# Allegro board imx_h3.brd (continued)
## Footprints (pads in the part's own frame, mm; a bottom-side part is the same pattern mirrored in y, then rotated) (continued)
RC0402_25
  round 0.635 smd: 1(-0.508,0) 2(0.508,0)
RC0603_OV
  oval 0.889x1.143 smd: 1(-0.762,0) 2(0.762,0)
RC0805_OV
  oval 0.889x1.524 smd: 1(-0.965,0) 2(0.965,0)
RCA8_16
  rect 0.66x0.406 smd: 1(-0.711,1.802) 8(-0.711,-1.802) 9(0.711,-1.802) 16(0.711,1.802)
  rect 0.66x0.305 smd: 2(-0.711,1.251) 3(-0.711,0.751) 4(-0.711,0.25) 5(-0.711,-0.25) 6(-0.711,-0.751) 7(-0.711,-1.251) 10(0.711,-1.251) 11(0.711,-0.751) 12(0.711,-0.25) 13(0.711,0.25) 14(0.711,0.751) 15(0.711,1.251)
SC70-5
  rect 0.406x0.813 smd: 1(-0.65,-1.079) 2(0,-1.079) 3(0.65,-1.079) 4(0.65,1.079) 5(-0.65,1.079)
SC70_3
  rect 0.711x0.889 smd: 1(-0.648,-0.952) 2(0.648,-0.952) 3(0,0.952)
SOD123
  rect 1.016x1.27 smd: A(1.651,0) C(-1.651,0)
SOD-123
  rect 1.321x1.219 smd: A(-1.626,0) C(1.626,0)
SOT23
  rect 0.762x1.219 smd: 1(-1.016,-1.092) 2(1.016,-1.092) 3(0,1.092)
SOT23-5
  rect 0.61x1.118 smd: 1(-1,-1.4) 2(-0.05,-1.4) 3(0.9,-1.4) 4(0.9,1.45) 5(-1,1.45)
SOT23-5_A
  rect 1.016x0.762 smd: 1(-1.3,0.95) 2(-1.3,0) 3(-1.3,-0.95) 4(1.3,-0.95) 5(1.3,0.95)
SOT23_5S
  rect 0.686x0.991 smd: 1(-0.953,-1.295) 2(0,-1.295) 3(0.953,-1.295) 4(0.953,1.295) 5(-0.953,1.295)
SOT223
  rect 1.194x2.21 smd: 1(-2.3,-3.1) 2(0,-3.1) 3(2.3,-3.1)
  rect 3.734x2.21 smd: 4(0,3.1)
SOT363
  rect 0.406x0.508 smd: 1(-0.65,-0.95) 2(0,-0.95) 3(0.65,-0.95) 4(0.65,0.95) 5(0,0.95) 6(-0.65,0.95)
SOT-23
  rect 1.016x1.397 smd: 1(-0.95,-1.1) 2(0.95,-1.1) 3(0,1.1)
SSOP16
  rect 2.032x0.406 smd: 1(-3.48,2.276) 2(-3.48,1.626) 3(-3.48,0.975) 4(-3.48,0.325) 5(-3.48,-0.325) 6(-3.48,-0.975) 7(-3.48,-1.626) 8(-3.48,-2.276) 9(3.48,-2.276) 10(3.48,-1.626) 11(3.48,-0.975) 12(3.48,-0.325) 13(3.48,0.325) 14(3.48,0.975) 15(3.48,1.626) 16(3.48,2.276)
SW2_SPST_PB_RA
  round 0.254 hole 1.245x0.889 unplated: (-1.499,0)
  round 0.254 hole 0.889 unplated: (1.499,0)
  rect 1.016x1.219 smd: 1(1.93,2.718) 2(1.93,-2.718)
  rect 1.397x1.27 smd: 3(-1.041,-2.667) 4(-1.041,2.667)
SW_SPST_PB_4P8X3P5_SM
  rect 1.6x1.016 smd: 1(2.625,0.85) 2(2.625,-0.85) 3(-2.625,0.85) 4(-2.625,-0.85)
TESTPOINT_35MIL
  round 0.889 smd: 1(0,0)
TESTPOINT_060_035MIL
  round 1.524 hole 0.889: 1(0,0)
TSOP48
  rect 2.54x0.305 smd: 1(-9.677,5.753) 2(-9.677,5.253) 3(-9.677,4.752) 4(-9.677,4.252) 5(-9.677,3.752) 6(-9.677,3.251) 7(-9.677,2.751) 8(-9.677,2.25) 9(-9.677,1.75) 10(-9.677,1.25) 11(-9.677,0.749) 12(-9.677,0.249) 13(-9.677,-0.249) 14(-9.677,-0.749) 15(-9.677,-1.25) 16(-9.677,-1.75) 17(-9.677,-2.25) 18(-9.677,-2.751) 19(-9.677,-3.251) 20(-9.677,-3.752) 21(-9.677,-4.252) 22(-9.677,-4.752) 23(-9.677,-5.253) 24(-9.677,-5.753) 25(9.677,-5.753) 26(9.677,-5.253) 27(9.677,-4.752) 28(9.677,-4.252) 29(9.677,-3.752) 30(9.677,-3.251) 31(9.677,-2.751) 32(9.677,-2.25) 33(9.677,-1.75) 34(9.677,-1.25) 35(9.677,-0.749) 36(9.677,-0.249) 37(9.677,0.249) 38(9.677,0.749) 39(9.677,1.25) 40(9.677,1.75) 41(9.677,2.25) 42(9.677,2.751) 43(9.677,3.251) 44(9.677,3.752) 45(9.677,4.252) 46(9.677,4.752) 47(9.677,5.253) 48(9.677,5.753)
TSSOP14_A
  rect 1.524x0.356 smd: 1(-2.959,1.951) 2(-2.959,1.3) 3(-2.959,0.65) 4(-2.959,0) 5(-2.959,-0.65) 6(-2.959,-1.3) 7(-2.959,-1.951) 8(2.959,-1.951) 9(2.959,-1.3) 10(2.959,-0.65) 11(2.959,0) 12(2.959,0.65) 13(2.959,1.3) 14(2.959,1.951)
unnamed#2
  round 1.016 smd: (0,0)
VLF5020
  custom 0.524x0.524 smd: 1(-1.699,0) 2(1.699,0)
XTAL2-3P2X1P5-SM
  rect 1.092x1.905 smd: 1(-1.25,0) 2(1.25,0)
XTAL_CS10_SM
  rect 2.007x2.489 smd: 1(-2.248,0) 2(2.248,0)
XTLOSC4_3P2X2P5MM_SM
  rect 1.397x1.194 smd: 1(-1.1,-0.8) 2(1.1,-0.8) 3(1.1,0.8) 4(-1.1,0.8)

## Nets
3V3_DEBUG: C205.1 C206.1 U34.16(VUSB33) U34.17(VUSB33_MON)
3V3_GATED: C29.1 C58.1 C147.1 C150.1 C152.1 C154.1 C155.1 C157.1 C183.1 C198.1 C215.1 C216.1 C221.1 C223.2 C249.1 C250.1 C271.1 C284.1 C285.1 C286.1 C287.1 C288.1 C294.1 D44.3(CATHODE) J20.2(3.3V_1) J20.3(RESERVED1) J20.4(GND7) J20.10(UIM_DATA) J20.12(UIM_CLK) L1.2 L12.1 L19.2 R9.1 R12.1 R13.2 R14.2 R64.1 R77.2 R81.1 R82.1 R128.1 R178.1 R204.1 U3.9(VDDIO) U14.1(VIN) U19.20(VDDIO) U41.7(VDDD)
3V3_GATED_EN: R143.1 U14.3(CE) U17.3(IO0_2) U29.3(EN)
3V3_ISM: C160.1 C161.1 C162.1 C163.1 C164.1 C165.1 C168.1 C169.1 C170.1 C190.1 C293.1 J11.6(B3) U4.1(VREFH) U4.19(VDD) U4.35(VBAT2) U4.43(VBAT1(RF)) U4.55(VDD1) U4.56(VDDAD) U42.5(VOUT)
3V3_MAIN: C85.1 C210.1 C211.1 C218.2 C227.1 C228.1 C229.1 C230.1 C281.1 C282.1 C283.1 L15.2 L18.2 R137.1 R138.1 R174.1 R212.1 U25.5(VDDA33_5) U25.10(VDDA33_10) U25.15(VDD33_15) U25.23(VDD33_23) U25.27(VBUS_DET) U25.29(VDD33_29) U25.36(VDD33_36)
4V2_BACKUP: C185.1 C196.1 C208.1 C220.1 C222.1 C292.1 L11.1 L20.1 Q6.4(S) Q13.4(S) R135.1 R155.1 R158.1 R172.1 R210.1 U16.2(VIN) U20.2(VIN) U28.1(VIN) U29.1(VIN) U30.5(3V3) U42.1(VIN)
4V2_BUCK: C201.1 C275.1 C276.1 C277.1 L16.2 Q5.4(S) R176.2 U22.1(BD) U22.7(BIAS)
4V2_PG: R155.2 S1.1(A1) U22.6(PG) U30.2(IN_A)
5V: C186.1 C256.1 C258.1 C259.1 C262.1 C278.1 C279.1 C280.1 C290.1 D11.C J13.2 J13.4 J13.7 J13.8 J13.11 J13.13 J13.39 J13.41 R98.1
5V_DEBUG: C35.1 C134.1 L5.1 Q17.1(GATE) Q18.1(GATE) Q19.1(GATE) Q20.1(GATE) R19.1 R68.1 R69.1 R214.2 U34.11(VDD)
5V_LCD_EN: U16.3(EN) U17.4(IO0_3)
5V_MAIN: C104.1 C105.1 C106.1 C202.1 C233.1 D45.C(CATHODE) F1.1 Q15.2(ANODE1) Q15.4(ANODE2) R44.1 TVS1.2 TVS2.2 U1.E17(VDD5V) U22.4(VIN) U22.5(RUN/SS)
5V_MAIN_PRESENT: J5.2 R44.2 U1.D3(SSP2_SS1/SSP2_D4/SSP2_D1/USB1_O) U30.1(IN_B)
5V_USB: C195.1 C231.1 C232.1 D12.C R132.1 U32.2(IN) U33.2(IN)
5V_USB_REG_EN: R158.2 U20.3(EN) U40.8(Y3)
GND: ANT1.2(GND) C1.2 C2.2 C3.2 C4.2 C5.2 C6.2 C7.2 C8.2 C9.2 C10.2 C11.2 C12.2 C13.2 C14.2 C15.2 C16.2 C17.2 C18.2 C19.2 C20.2 C21.2 C22.2 C23.2 C25.2 C26.2 C27.2 C28.2 C29.2 C30.2 C31.2 C32.2 C33.2 C34.2 C35.2 C51.2 C52.2 C57.2 C58.2 C59.2 C60.2 C61.2 C62.2 C63.2 C64.2 C65.2 C66.2 C67.2 C68.2 C69.2 C70.2 C71.2 C72.2 C73.2 C74.2 C75.2 C76.2 C77.2 C78.2 C79.2 C80.2 C81.2 C82.2 C83.2 C84.2 C85.2 C86.2 C87.2 C88.2 C89.2 C90.2 C91.2 C92.2 C93.2 C94.2 C95.2 C96.2 C97.2 C98.2 C99.2 C100.2 C101.2 C102.2 C103.2 C105.2 C106.2 C107.2 C108.1 C109.2 C110.2 C111.2 C112.2 C113.2 C114.2 C115.2 C116.2 C117.2 C118.2 C119.2 C120.2 C121.2 C122.2 C123.2 C124.2 C125.2 C126.2 C127.2 C128.2 C129.2 C130.2 C131.2 C132.2 C133.2 C134.2 C135.2 C136.2 C137.2 C138.2 C139.2 C140.2 C141.2 C142.1 C143.2 C144.2 C145.2 C146.1 C147.2 C148.2 C149.2 C150.2 C151.2 C152.2 C153.2 C154.2 C155.2 C156.2 C157.2 C158.2 C159.2 C160.2 C161.2 C162.2 C163.2 C164.2 C165.2 C166.1 C167.2 C168.2 C169.2 C170.2 C171.2 C172.1 C173.2 C174.2 C175.2 C176.2 C178.2 C179.2 C180.2 C183.2 C184.2 C185.2 C186.2 C187.2 C188.2 C189.2 C190.2 C192.2 C194.2 C195.2 C196.2 C197.1 C198.2 C199.2 C200.1 C201.2 C202.2 C203.2 C205.2 C206.2 C207.2 C208.2 C209.2 C210.2 C211.2 C212.2 C213.2 C214.2 C215.2 C216.2 C217.2 C219.1 C220.2 C221.2 C222.2 C224.1 C225.2 C226.2 C227.2 C228.2 C229.2 C230.2 C231.2 C232.2 C233.2 C234.2 C235.2 C236.2 C237.2 C238.2 C239.2 C240.2 C241.2 C243.2 C244.2 C245.2 C246.2 C247.2 C248.2 C249.2 C250.2 C251.2 C252.2 C253.2 C254.2 C255.2 C256.2 C257.2 C258.2 C259.2 C260.2 C261.2 C262.2 C263.2 C264.2 C265.2 C266.2 C267.2 C268.2 C269.2 C270.2 C271.2 C272.2 C273.2 C274.2 C275.2 C276.2 C277.2 C278.2 C279.2 C280.2 C281.2 C282.2 C283.2 C284.2 C285.2 C286.2 C287.2 C288.2 C289.2 C290.2 C291.2 C292.2 C293.2 C294.2 C295.2 C296.2 C297.2 C298.2 C300.2 D17.A D43.3 D44.1(ANODE) E5.1 E6.1 FL1.1(GND1) FL1.2(GND2) FL2.1(GND1) FL2.2(GND2) FL3.1(GND1) FL3.2(GND2) FL4.1(GND1) FL4.2(GND2) FL5.1(GND1) FL5.2(GND2) FL6.1(GND1) FL6.2(GND2) FL7.1(GND1) FL7.2(GND2) FL8.1(GND1) FL8.2(GND2) J5.3 J9.2(GND1) J9.3(GND2) J10.2(GND1) J10.3(GND2) J11.2(B1) J12.2(GND1) J12.3(GND2) J13.6 J13.12 J13.18 J13.23 J13.24 J13.30 J13.36 J13.42 J13.48 J13.54 J13.60 J13.93 J13.103 J13.SH1 J13.SH2 J13.SH3 J13.SH4 J13.SH5 J13.SH6 J13.SH7 J13.SH8 J14.2(GND1) J14.3(GND2) J16.2 J17.3 J20.6(1.5V_1) J20.8(UIM_PWR) J20.9(GND1) J20.13(REFCLK+) J20.14(UIM_RESET) J20.24(+3.3VAUX) J20.26(GND9) J20.48(1.5V_3) J20.50(GND12) J20.52(3.3V_2) J23.2 L4.2 L13.2 L23.1 L25.1 L26.1 L30.2 P2.9 P2.10 Q4.2(SOURCE) Q9.2(SOURCE) Q15.1(CATHODE) Q16.2(SOURCE) R3.2 R11.2 R15.2 R16.1 R18.1 R20.2 R27.2 R42.2 R43.2 R57.2 R58.2 R75.2 R76.2 R78.1 R80.2 R96.2 R103.2 R119.2 R120.2 R122.2 R123.2 R129.2 R130.2 R131.2 R136.2 R141.2 R142.2 R143.2 R147.2 R148.2 R150.2 R166.1 R167.1 R168.2 R169.1 R169.2 R170.2 R171.1 R171.2 R173.2 R175.2 R177.2 R208.1 R214.1 S1.3(B2) S1.4(B1) SW3.2 SW3.4 SW5.2 SW6.1 SW7.2 SW7.4 SW8.1 T1.7(NC) T1.8(GND) T1.13(GND_13) T1.14(GND_14) TP3.1(TP) TP4.1(TP) TP5.1(TP) TVS1.1 TVS2.1 U1.A1(VSS1) U1.A9(VSS2) U1.A17(DCDC_GND) U1.B7(VSS3) U1.B11(VSSA2_A) U1.B13(VSSA1) U1.C10(TESTMODE) U1.C16(VSS4) U1.E5(VSS5) U1.E15(VSS6) U1.F14(VSSIO_EMI10) U1.F16(VSSIO_EMI9) U1.H3(VSS7) U1.H9(VSS8) U1.H10(VSS9) U1.H11(VSS10) U1.H12(VSS11) U1.H14(VSSIO_EMI8) U1.H16(VSS12) U1.J11(VSS13) U1.J12(VSS14) U1.J15(VSS15) U1.K9(VSS16) U1.K10(VSS17) U1.K11(VSS18) U1.L10(VSS19) U1.L11(VSS20) U1.L12(VSSIO_EMI7) U1.M14(VSS21) U1.M16(VSSIO_EMI6) U1.N4(VSS22) U1.P14(VSSIO_EMI4) U1.P16(VSSIO_EMI5) U1.R10(VSSIO_EMI_11) U1.R12(VSSIO_EMI1) U1.T14(VSSIO_EMI3) U1.U1(VSS23) U1.U17(VSSIO_EMI2) U2.A3(VSS1) U2.A7(VSSQ2) U2.B2(VSSQ3) U2.B8(VSSQ1) U2.D2(VSSQ4) U2.D8(VSSQ5) U2.E3(VSS2) U2.E7(VSSQ6) U2.F2(VSSQ7) U2.F8(VSSQ8) U2.H2(VSSQ9) U2.H8(VSSQ10) U2.J3(VSS3) U2.J7(VSSDL) U2.N1(VSS4) U2.P9(VSS5) U3.25(VSS) U4.2(VREFL) U4.3(VSSAD) U4.4(VSS1) U4.20(VSS2) U4.36(GND) U4.38(GND_PA2(RF)) U4.40(GND_PA1(RF)) U4.61(VSS3) U4.62(VSS4) U5.13(VSS1) U5.36(VSS2) U14.2(GND) U15.58(RF_GND) U15.75(VSS_1) U15.76(VSS_2) U15.77(VSS_3) U15.78(VSS_4) U15.79(VSS_5) U15.84(VSS_6) U15.85(VSS_7) U15.86(VSS_8) U15.87(VSS_9) U15.88(VSS_10) U15.93(VSS_11) U15.94(VSS_12) U15.95(VSS_13) U15.96(VSS_14) U15.97(VSS_15) U15.104(VSS_16) U15.105(VSS_17) U15.106(VSS_18) U15.115(VSS_19) U16.1(PGND) U16.5(AGND) U16.7(EP) U17.9(VSS) U17.23(A1) U17.25(EP) U19.1(GND1) U19.3(GND2) U19.7(AGND) U19.33(GND3-PAD) U20.1(PGND) U20.5(AGND) U20.7(EP) U22.11(GND) U25.37(VSS_EPAD) U28.2(GND) U29.2(GND) U30.3(DGND) U31.3(DGND) U32.1(GND) U32.9(PAD) U33.1(GND) U33.9(PAD) U34.13(VSS) U34.23(VSSOSC) U34.25(EP) U40.7(GND) U41.5(N\R\D\) U41.6(N\W\R\) U41.10(GND) U41.16(GNDA) U42.2(GND) Y3.2(GND#2) Y3.4(GND#4) Y4.2 Y4.4 Y5.2(GND#2) Y5.4(GND#4) Y7.2(GND#2) Y7.4(GND#4) Y8.2(GND#2) Y8.4(GND#4)
VBUS_BOT: C235.1 C239.1 L22.1 U32.6(OUT2)
VBUS_MODEM: C237.1 C238.1 L24.1 U33.6(OUT2)
VBUS_OTG: C236.1 C241.1 C254.1 D4.C L3.1 R93.2
VBUS_TOP: C234.1 C240.1 L21.1 U32.7(OUT1)
VDD1P5_1V5: C119.1 C120.1 C121.1 C122.1 C123.1 U1.D16(VDD1P5)
VDD_1V5: C291.1 J13.111 J13.113 J13.115
VDD_4P2: C129.1 C130.1 C131.1 C132.1 C133.1 U1.A13(VDD4P2)
VDD_XTAL: C140.1 SW2.2 U1.C12(VDDXTAL)
ADC_BATT: C153.1 R165.2 U1.C15(LRADC0)
BKGD: J11.1(A1) U4.34(PTA4/ACMP1O/BKGD/MS)
BT_ACTIVE: J20.41(RESERVED5) R101.1
BT_HOST_WAKE: J20.43(RESERVED6) U17.13(IO1_3)
BT_RESET_B: J20.42(LED_WWAN#) U17.16(IO1_6)
BUTTON_1: R127.1 R151.1 U1.B5(SSP0_DATA4/SSP2_D0/GPIO2_4)
BUTTON_2: R124.1 R144.1 U1.C5(SSP0_DATA5/SSP2_D3/GPIO2_5)
BUTTON_3: R140.1 R153.2 U1.D5(SSP0_DATA6/SSP2_CMD/GPIO2_6)
BUTTON_4: R126.1 R152.2 U1.D10(SSP0_DETECT/GPIO2_9)
DCDC_VDDA_1V8: C1.1 C2.1 C3.1 C4.1 C5.1 C6.1 C7.1 C8.1 C9.1 C10.1 C11.1 C12.1 C13.1 C14.1 C15.1 C16.1 C17.1 C18.1 C19.1 C20.1 C21.1 C22.1 C23.1 C24.1 C74.1 C75.1 C76.1 C77.1 C78.1 C79.1 C80.1 C81.1 C83.1 C84.1 C86.1 C87.1 C88.1 C89.1 C90.1 C91.1 C92.1 C93.1 C94.1 C95.1 C98.1 C109.1 C110.1 C111.1 C112.1 C113.1 C245.1 C246.1 C257.1 C261.1 C264.1 J13.1 J13.17 J13.19 J13.25 R2.1 U1.B16(DCDC_VDDA) U1.C13(VDDA1) U1.F8(VDDIO18_0) U1.F9(VDDIO18_1) U1.G8(VDDIO18_2) U1.G9(VDDIO18_3) U1.G13(VDDIO_EMI_8_1) U1.G15(VDDIO_EMI_8_2) U1.G17(VDDIO_EMI_8_3) U1.J13(VDDIO_EMIQ2) U1.K15(VDDIO_EMIQ1) U1.L13(VDDIO_EMI_7) U1.M10(VDDIO_EMI_0) U1.M11(VDDIO_EMI_3_1) U1.M12(VDDIO_EMI_3_2) U1.N13(VDDIO_EMI_3_3) U1.N15(VDDIO_EMI_6) U1.P11(VDDIO_EMI_1) U1.R13(VDDIO_EMI_3_4) U1.R15(VDDIO_EMIQ0) U2.A1(VDD1) U2.A9(VDDQ6) U2.C1(VDDQ2) U2.C3(VDDQ3) U2.C7(VDDQ4) U2.C9(VDDQ5) U2.E1(VDD2) U2.E9(VDDQ1) U2.G1(VDDQ7) U2.G3(VDDQ8) U2.G7(VDDQ9) U2.G9(VDDQ10) U2.J1(VDDL) U2.J9(VDD3) U2.M9(VDD4) U2.R1(VDD5)
DCDC_VDDD_1V2: C57.1 C59.1 C60.1 C62.1 C63.1 C114.1 C115.1 C116.1 C117.1 C118.1 U1.D17(DCDC_VDDD) U1.F10(VDDD0) U1.F11(VDDD1) U1.F12(VDDD2) U1.G10(VDDD3) U1.G11(VDDD4) U1.G12(VDDD5) U1.K12(VDDD6)
DCDC_VDDIO_3V3: C51.1 C52.1 C64.1 C65.1 C66.1 C67.1 C69.1 C70.1 C71.1 C72.1 C73.1 C96.1 C97.1 C99.1 C100.1 C101.1 C102.1 C103.1 C187.1 C217.1 C255.1 C260.1 C265.1 C266.1 C272.1 J13.5 J13.45 J13.47 J13.49 J20.1(WAKE#) J20.32(SMB_DATA) P2.1 R17.1 R25.1 R26.1 R45.2 R49.2 R51.1 R52.1 R53.1 R54.1 R55.1 R56.1 R66.2 R104.1 R105.1 R109.1 R118.1 R124.2 R126.2 R134.2 R140.2 R151.2 R213.2 U1.A7(VDDIO33_8) U1.C17(DCDC_VDDIO) U1.E6(VDDIO33_0) U1.E16(VDDIO33_7) U1.G3(VDDIO33_1) U1.H8(VDDIO33_5_1) U1.J8(VDDIO33_5_2) U1.J9(VDDIO33_5_3) U1.J10(VDDIO33_5_4) U1.N3(VDDIO33_4) U1.N17(VDDIO33_EMI) U5.12(VCC1) U5.37(VCC2) U17.18(A0) U17.21(VDD) U17.24(A2) U31.5(3V3) U40.14(VCC)
DDR2_A0: U1.U15(EMI_A00) U2.M8(A0)
DDR2_A1: U1.U12(EMI_A01) U2.M3(A1)
DDR2_A2: U1.U14(EMI_A02) U2.M7(A2)
DDR2_A3: U1.T11(EMI_A03) U2.N2(A3)
DDR2_A4: U1.U10(EMI_A04) U2.N8(A4)
DDR2_A5: U1.R11(EMI_A05) U2.N3(A5)
DDR2_A6: U1.R9(EMI_A06) U2.N7(A6)
DDR2_A7: U1.N11(EMI_A07) U2.P2(A7)
DDR2_A8: U1.U9(EMI_A08) U2.P8(A8)
DDR2_A9: U1.P10(EMI_A09) U2.P3(A9)
DDR2_A10: U1.U13(EMI_A10) U2.M2(A10)
DDR2_A11: U1.T10(EMI_A11) U2.P7(A11)
DDR2_A12: U1.U11(EMI_A12) U2.R2(A12)
DDR2_A13: U1.T9(EMI_A13) U2.R8(NC/A13)
DDR2_A14: U1.N10(EMI_A14) U2.R3(NC/A14)
DDR2_BA0: U1.T16(EMI_BA0) U2.L2(BA0)
DDR2_BA1: U1.T12(EMI_BA1) U2.L3(BA1)
DDR2_BA2: U1.N12(EMI_BA2) U2.L1(NC/BA2)
DDR2_CAS_B: U1.U16(E\M\I\_\C\A\S\) U2.L7(CAS#)
DDR2_CKE: R58.1 U1.T13(EMI_CKE) U2.K2(CKE)
DDR2_CLK: R1.1 U1.L17(EMI_CLK) U2.J8(CK)
DDR2_CLK_B: R1.2 U1.L16(E\M\I\_\C\L\K\) U2.K8(CK#)
DDR2_CS_B: U1.P12(E\M\I\_\C\E\0\) U2.L8(CS#)
DDR2_D00: U1.N16(EMI_D00) U2.H1(DQ4)
DDR2_D01: U1.M13(EMI_D01) U2.G2(DQ1)
DDR2_D02: U1.P15(EMI_D02) U2.H3(DQ3)
DDR2_D03: U1.N14(EMI_D03) U2.F1(DQ6)
DDR2_D04: U1.P13(EMI_D04) U2.H7(DQ2)
DDR2_D05: U1.P17(EMI_D05) U2.H9(DQ5)
DDR2_D06: U1.L14(EMI_D06) U2.F9(DQ7)
DDR2_D07: U1.M17(EMI_D07) U2.G8(DQ0)
DDR2_D08: U1.G16(EMI_D08) U2.C8(DQ8)
DDR2_D09: U1.H15(EMI_D09) U2.D7(DQ10)
DDR2_D10: U1.G14(EMI_D10) U2.C2(DQ9)
DDR2_D11: U1.J14(EMI_D11) U2.D3(DQ11)
DDR2_D12: U1.H13(EMI_D12) U2.D1(DQ12)
DDR2_D13: U1.H17(EMI_D13) U2.D9(DQ13)
DDR2_D14: U1.F13(EMI_D14) U2.B1(DQ14)
DDR2_D15: U1.F17(EMI_D15) U2.B9(DQ15)
DDR2_DQM0: U1.M15(EMI_DQM0) U2.F3(LDM)
DDR2_DQM1: U1.F15(EMI_DQM1) U2.B3(UDM)
DDR2_DQS0: U1.K17(EMI_DQS0) U2.F7(LDQS)
DDR2_DQS0_B: U1.K16(E\M\I\_\D\Q\S\0\) U2.E8(LDQSN)
DDR2_DQS1: U1.J17(EMI_DQS1) U2.B7(UDQS)
DDR2_DQS1_B: U1.J16(E\M\I\_\D\Q\S\1\) U2.A8(UDQSN)
DDR2_ODT0: U1.R17(EMI_ODT0) U2.K9(ODT)
DDR2_OPEN: U1.K14(EMI_DDR_OPEN) U1.L15(EMI_DDR_OPEN_FB)
DDR2_RAS_B: U1.R16(E\M\I\_\R\A\S\) U2.K7(RAS#)
DDR2_VREF: C24.2 C25.1 R2.2 R3.1 U1.K13(EMI_VREF1) U1.R14(EMI_VREF0) U2.J2(VREF)
DDR2_WE_B: U1.T15(E\M\I\_\W\E\) U2.K3(WE#)
DEBUG_GND: C305.2 J8.5(P5) J8.S1(SHLD1) J8.S2(SHLD2) J8.S3(SHLD3) J8.S4(SHLD4) R208.2
DIG_REG: U15.124(DIG_REG)
DUAL_GND: C302.2 C303.2 J22.A4(GND) J22.B4(GND_B) J22.S1(SGND1) J22.S2(SGND2) J22.S3(SGND3) J22.S4(SGND4) L23.2 L25.2
DUART_RX: Q19.2(SOURCE) R213.1 U1.K7(PWM0/I2C1_SCL/DUART_RX/GPIO3_16)
DUART_TX: Q17.2(SOURCE) U1.L7(PWM1/I2C1_SDA/DUART_TX/GPIO3_17)
EN_BOT: U25.18(PRTPWR3) U32.4(EN2) U40.4(A2)
EN_MODEM: R108.2 U31.4(OUT) U33.4(EN2) U40.12(A4)
EN_TOP: U25.16(PRTPWR2) U32.3(EN1) U40.5(B2)
ENET_CLKO: R180.1 U1.E2(ENET_CLK/GPIO4_16)
ENET_INT: R13.1 U3.14(IN\T\/REFCLKO) U17.11(IO1_1)
ENET_MDC: R182.1 U1.G4(ENET0_MDC/G\P\M\I\_\C\E\4\/SAIF)
ENET_MDIO: R181.1 U1.H4(ENET0_MDIO/G\P\M\I\_\C\E\5\/SAI)
ENET_RESET_B: R12.2 U3.15(R\S\T\) U17.7(IO0_6)
ENET_RXD0: R183.1 U1.H1(ENET0_RXD0/G\P\M\I\_\C\E\7\/SAI)
ENET_RXD1: R184.1 U1.H2(ENET0_RXD1/GPMI_READY4/GPIO4_4)
ENET_RXEN: R185.1 U1.E4(ENET0_RX_EN/G\P\M\I\_\C\E\6\/SA)
ENET_TXD0: R186.1 U1.F1(ENET0_TXD0/GPMI_READY6/GPIO4_7)
ENET_TXD1: R187.1 U1.F2(ENET0_TXD1/GPMI_READY7/GPIO4_8)
ENET_TXEN: R188.1 U1.F4(ENET0_TX_EN/GPMI_READY5/GPIO4_6)
ETH_RXN: R5.2 T1.6(RD-) U3.22(RXN)
ETH_RXP: R4.2 T1.3(RD+) U3.23(RXP)
ETH_TXN: R8.2 T1.2(TD-) U3.20(TXN)
ETH_TXP: R7.2 T1.1(TD+) U3.21(TXP)
FEC_A3V3: C26.1 C27.1 C28.1 C30.1 C247.1 C248.1 C251.1 C252.1 L1.1 R4.1 R5.1 R6.1 R7.1 R8.1 R10.2 U3.1(VDD2A) U3.19(VDD1A)
HP_GND: J15.2 J18.1 L13.1 U19.4(HP_VGND)
HP_L: C213.1 C267.1 J15.1 J18.3 U19.6(HP_L)
HP_R: C212.1 C268.1 J15.3 J18.2 U19.2(HP_R)
I2C_SCL: R95.2 R104.2 U1.C7(I2C0_SCL/TIMROT_ROTARYA/DUART_R) U4.24(PTA3/KBI1P3/SCL/ADP3) U17.19(SCL) U19.29(CTRL_CLK)
I2C_SCL_IO_EXP: J13.31
I2C_SDA: R94.2 R105.2 U1.D8(I2C0_SDA/TIMROT_ROTARYB/DUART_T) U4.25(PTA2/KBI1P2/SDA/ADP2) U17.20(SDA) U19.27(CTRL_DATA)
I2C_SDA_IO_EXP: J13.29
IO_EXP_INT_B: R109.2 U1.N8(GPMI_RDY1/SSP1_CMD/GPIO0_21) U17.22(\I\N\T\)
ISM_DIO5: TP8.1(PIN1) U4.5(EXTAL/SCL/PTB7) U4.54(DIO5/CLKOUT)
ISM_DIR: U4.32(PTC4/TPM3CH4) U4.37(RXTX(RF))
ISM_GPIO: U4.14(PTB2/KBI1P6/ADP6) U17.14(IO1_4)
ISM_LED: R206.1 U4.8(PTB4/TPM2CH1)
ISM_RESET_B: J11.4(B2) R66.1 U4.33(PTA5/IRQ/TPM1CLK/R\E\S\E\T\) U17.8(IO0_7)
ISM_RF_RESET: U4.12(PTC0/TPM3CH0) U4.48(R\E\S\E\T\)
ISM_RFIO: L7.1 U4.39(RFIO(RF))
ISM_UART_RX: TP14.1(PIN1) U4.15(PTB1/KBI1P5/TXD1/ADP5)
ISM_UART_TX: TP13.1(PIN1) U4.16(PTB0/KBI1P4/RXD1/ADP4)
ISM_XTA: C171.1 U4.46(XTA) Y4.1
ISM_XTB: C172.2 U4.47(XTB) Y4.3
JTAG_MX_TDI: R159.1 R164.1 U1.E12(JTAG_TDI)
JTAG_MX_TDO: R160.2 R163.2 U1.E13(JTAG_TDO)
JTAG_RTCK: P2.6 R56.2 R125.2 U1.E14(JTAG_RTCK/GPIO4_20)
JTAG_TCK: P2.5 R52.2 R57.1 U1.E11(JTAG_TCK) U15.11(TCK/GPIO47)
JTAG_TDI: P2.3 R51.2 R159.2 R162.2
JTAG_TDO: P2.7 R53.2 R161.1 R163.1
JTAG_TMS: P2.4 R55.2 U1.D12(JTAG_TMS) U15.12(TMS/GPIO46)
JTAG_TRST_B: P2.2 R54.2 R146.1 U1.D14(JTAG_TRST)
JTAG_ZB_TDI: R160.1 R162.1 U15.10(TDI/GPIO48)
JTAG_ZB_TDO: R161.2 R164.2 U15.9(TDO/GPIO49)
LAN_LED_G: T1.10(GLED-) U3.2(LED2/IN\T\S\E\L\)
LAN_LED_Y: T1.11(YLED+) U3.3(LED1/REGOFF)
LCD_BL_PWM: FL1.4(IN(OUT)2) U1.E10(PWM4/GPIO3_29)
LCD_BL_PWM_EMI: FL1.8(OUT(IN)2) J13.112 R92.2
LCD_CARD_PRESENT: J13.83 U17.17(IO1_7)
LCD_CS: FL8.6(IN(OUT)4) U1.P5(LCD_CS/LCD_ENABLE/GPIO1_27)
LCD_CS_CON: J13.105 R83.1
LCD_CS_EMI: FL8.10(OUT(IN)4) R83.2 R84.2
LCD_D0: FL7.3(IN(OUT)1) R119.1 U1.K2(LCD_D00/ETM_DA0/GPIO1_0)
LCD_D0_EMI: FL7.7(OUT(IN)1) J13.62
LCD_D1: FL7.4(IN(OUT)2) R120.1 U1.K3(LCD_D01/ETM_DA1/GPIO1_1)
LCD_D1_EMI: FL7.8(OUT(IN)2) J13.64
LCD_D2: FL7.5(IN(OUT)3) R121.1 U1.L2(LCD_D02/ETM_DA2/GPIO1_2)
LCD_D2_EMI: FL7.9(OUT(IN)3) J13.66
LCD_D3: FL7.6(IN(OUT)4) R122.1 U1.L3(LCD_D03/ETM_DA3/ETM_DA8/GPIO1_3)
LCD_D3_EMI: FL7.10(OUT(IN)4) J13.68
LCD_D4: FL6.3(IN(OUT)1) R123.1 U1.M2(LCD_D04/ETM_DA4/ETM_DA9/GPIO1_4)
LCD_D4_EMI: FL6.7(OUT(IN)1) J13.70
LCD_D5: FL6.4(IN(OUT)2) U1.M3(LCD_D05/ETM_DA5/GPIO1_5)
LCD_D5_EMI: FL6.8(OUT(IN)2) J13.72
LCD_D6: FL6.5(IN(OUT)3) Q16.1(GATE) R212.2 U1.N2(LCD_D06/ETM_DA6/GPIO1_6)
LCD_D6_EMI: FL6.9(OUT(IN)3) J13.74
LCD_D7: FL6.6(IN(OUT)4) R46.1 U1.P1(LCD_D07/ETM_DA7/GPIO1_7)
LCD_D7_EMI: FL6.10(OUT(IN)4) J13.76
LCD_D8: FL5.3(IN(OUT)1) RN7.1(A) U1.P2(LCD_D08/ETM_DA8/ETM_DA3/GPIO1_8)
LCD_D8_EMI: FL5.7(OUT(IN)1) J13.78
LCD_D9: FL5.4(IN(OUT)2) RN7.2(A) U1.P3(LCD_D09/ETM_DA9/ETM_DA4/GPIO1_9)
LCD_D9_EMI: FL5.8(OUT(IN)2) J13.80
LCD_D10: FL5.5(IN(OUT)3) RN7.3(A) U1.R1(LCD_D10/ETM_DA10/GPIO1_10)
LCD_D10_EMI: FL5.9(OUT(IN)3) J13.82
LCD_D11: FL5.6(IN(OUT)4) RN7.4(A) U1.R2(LCD_D11/ETM_DA11/GPIO1_11)
LCD_D11_EMI: FL5.10(OUT(IN)4) J13.84
LCD_D12: FL4.3(IN(OUT)1) RN7.5(A) U1.T1(LCD_D12/ETM_DA12/GPIO1_12)
LCD_D12_EMI: FL4.7(OUT(IN)1) J13.86
LCD_D13: FL4.4(IN(OUT)2) RN7.6(A) U1.T2(LCD_D13/ETM_DA13/GPIO1_13)
LCD_D13_EMI: FL4.8(OUT(IN)2) J13.88
LCD_D14: FL4.5(IN(OUT)3) RN7.7(A) U1.U2(LCD_D14/ETM_DA14/GPIO1_14)
LCD_D14_EMI: FL4.9(OUT(IN)3) J13.90
LCD_D15: FL4.6(IN(OUT)4) RN7.8(A) U1.U3(LCD_D15/ETM_DA15/GPIO1_15)
LCD_D15_EMI: FL4.10(OUT(IN)4) J13.92
LCD_D16: FL3.3(IN(OUT)1) RN6.1(A) U1.T3(LCD_D16/ETM_DA7/GPIO1_16)
LCD_D16_EMI: FL3.7(OUT(IN)1) J13.94
LCD_D17: FL3.4(IN(OUT)2) R207.1 U1.R3(LCD_D17/ETM_DA6/GPIO1_17)
LCD_D17_EMI: FL3.8(OUT(IN)2) J13.96
LCD_D18: FL3.5(IN(OUT)3) RN6.3(A) U1.U4(LCD_D18/ETM_DA5/GPIO1_18)
LCD_D18_EMI: FL3.9(OUT(IN)3) J13.98
LCD_D19: FL3.6(IN(OUT)4) R107.1 U1.T4(LCD_D19/ETM_DA4/GPIO1_19)
LCD_D19_EMI: FL3.10(OUT(IN)4) J13.100
LCD_D20: FL2.3(IN(OUT)1) RN6.5(A) U1.R4(LCD_D20/ENET1_1588_EVENT2_OUT/E)
LCD_D20_EMI: FL2.7(OUT(IN)1) J13.102
LCD_D21: FL2.4(IN(OUT)2) R100.1 U1.U5(LCD_D21/ENET1_1588_EVENT2_IN/ET)
LCD_D21_EMI: FL2.8(OUT(IN)2) J13.104
LCD_D22: FL2.5(IN(OUT)3) RN6.7(A) U1.T5(LCD_D22/ENET1_1588_EVENT3_OUT/E)
LCD_D22_EMI: FL2.9(OUT(IN)3) J13.106
LCD_D23: FL2.6(IN(OUT)4) R106.1 U1.R5(LCD_D23/ENET1_1588_EVENT3_IN/ET)
LCD_D23_EMI: FL2.10(OUT(IN)4) J13.108
LCD_DOTCLK: J13.43 R87.1
LCD_ENABLE: J13.116 R84.1
LCD_HSYNC: J13.114 R89.1
LCD_PWR_EN: J13.79 U1.M6(LCD_RESET/LCD_VSYNC/GPIO3_30)
LCD_RD_E: FL8.5(IN(OUT)3) U1.P4(LCD_RD_E/LCD_VSYNC/ETM_TCTL/GPI)
LCD_RD_E_CON: R85.2 R90.1
LCD_RD_E_EMI: FL8.9(OUT(IN)3) R90.2 R91.2
LCD_RS: FL8.3(IN(OUT)1) U1.M4(LCD_RS/LCD_DOTCLK/GPIO1_26)
LCD_RS_CON: J13.119 R86.1
LCD_RS_EMI: FL8.7(OUT(IN)1) R86.2 R87.2
LCD_RW_B: FL8.4(IN(OUT)2) U1.K1(LCD_WR_RWN/LCD_HSYNC/ETM_TCLK/G)
LCD_RW_B_EMI: FL8.8(OUT(IN)2) R88.2 R89.2
LCD_VSYNC: J13.110 R91.1
LCD_WR_RWN_CON: J13.109 R88.1
LI-ION_BATTERY: C124.1 C125.1 C126.1 C127.1 C128.1 C263.1 C289.1 J13.65 J13.67 J13.69 J13.71 J17.1 Q14.4(S) U1.A15(BATTERY) U1.B15(DCDC_BATT)
LRADC1: U1.C9(LRADC1)
LRADC2: C139.1 J13.99 U1.C8(LRADC2)
LRADC3: C138.1 J13.95 U1.D9(LRADC3)
LRADC4: C137.1 J13.101 U1.D13(LRADC4)
LRADC5: C136.1 J13.97 U1.D15(LRADC5)
LRADC6: C135.1 J13.38 U1.C14(LRADC6)
MIC: C159.1 C270.1 C299.2 U19.15(MIC)
MIC_BIAS: C158.1 C269.1 C300.1 J16.3 R209.1 U19.16(MIC_BIAS)
MODEM_GND: C301.2 L26.2 U35.4(GND_B) U35.S1 U35.S2 U35.S3 U35.S4
MODEM_VBUS_EN: U1.D7(SPDIF/ENET1_RX_ER/GPIO3_27) U31.1(IN_B)
NAND_ALE: U1.P6(GPMI_ALE/SSP3_D1/SSP3_D4/GPIO0_) U5.17(ALE)
NAND_CE_B: R25.2 U1.N7(G\P\M\I\_\C\E\0\/SSP3_D0/GPIO0_) U5.9(C\E\)
NAND_CLE: U1.P7(GPMI_CLE/SSP3_D2/SSP3_D5/GPIO0_) U5.16(CLE)
NAND_DAT0: U1.U8(GPMI_D00/SSP1_D0/GPIO0_0) U5.29(IO0)
NAND_DAT1: U1.T8(GPMI_D01/SSP1_D1/GPIO0_1) U5.30(IO1)
NAND_DAT2: U1.R8(GPMI_D02/SSP1_D2/GPIO0_2) U5.31(IO2)
NAND_DAT3: U1.U7(GPMI_D03/SSP1_D3/GPIO0_3) U5.32(IO3)
NAND_DAT4: U1.T7(GPMI_D04/SSP1_D4/GPIO0_4) U5.41(IO4)
NAND_DAT5: U1.R7(GPMI_D05/SSP1_D5/GPIO0_5) U5.42(IO5)
NAND_DAT6: U1.U6(GPMI_D06/SSP1_D6/GPIO0_6) U5.43(IO6)
NAND_DAT7: U1.T6(GPMI_D07/SSP1_D7/GPIO0_7) U5.44(IO7)
NAND_RB_B: R26.2 U1.N6(GPMI_RDY0/SSP1_CARD_DETECT/USB0) U5.7(READY/B\U\S\Y\)
NAND_RE_B: U1.R6(G\P\M\I\_\R\D\/SSP3_SCK/GPIO0_2) U5.8(R\E\)
NAND_WP_B: R27.1 U1.L9(G\P\M\I\_\R\E\S\E\T\/SSP3_CMD/G) U5.19(W\P\)
NAND_WR_B: U1.P8(G\P\M\I\_\W\R\/SSP1_SCK/GPIO0_2) U5.18(W\E\)
NVM_REG: U15.133(NVM_REG)
OC_BOT: U25.19(OCS3_N) U32.5(O\C\2\)
OC_MODEM: U25.13(OCS1_N) U33.5(O\C\2\)
OC_TOP: U25.17(OCS2_N) U32.8(O\C\1\)
OTG_GND: C304.2 J7.5(P5) J7.S1(SHLD1) J7.S2(SHLD2) J7.S3(SHLD3) J7.S4(SHLD4) L4.1
PICOREAD_ANT1: D43.2 L27.1 U41.8(ANT1)
PICOREAD_ANT2: D43.1 L28.1 U41.9(ANT2)
PICOREAD_REC: R179.1 U41.15(REC)
PICOREAD_SPI_MISO: RN8.7(PIN7) RN9.6(PIN6) U41.2(DOUT/AD1)
PICOREAD_SPI_MOSI: RN8.5(PIN5) RN9.8(PIN8) U41.3(DIN/AD0)
PICOREAD_SPI_SCK: RN8.8(PIN8) RN9.5(PIN5) U41.4(SCK/IRQ)
PICOREAD_SPI_SS: RN8.6(PIN6) RN9.7(PIN7) U41.1(C\S\)
PICOREAD_VDDA: C175.1 C273.1 C274.1 R204.2 U41.14(VDDA)
PICOREAD_XTAL1: C243.1 U41.12(XTAL1) Y9.1
PICOREAD_XTAL2: C244.1 U41.11(XTAL2) Y9.2
PSWITCH: R39.1 U1.A11(PSWITCH)
RESET_IN_B: P2.8 R45.1 SW3.1 SW3.3 U1.A14(R\E\S\E\T\)
RF_BIAS: U15.55(RF_BIAS)
RF_PLL_FLT: U15.46(RF_PLL_FLT)
RXER/PHYAD0: R14.1 R16.2 U3.10(RXER/PHYAD0)
SAIF0_BITCLK: R202.1 U1.F7(SAIF0_BITCLK/PWM_5/AUART4_RX/GP)
SAIF0_DIN: R199.1 U1.E8(SAIF1_SDATA0/PWM_7/SAIF0_SDATA1)
SAIF0_DOUT: R200.1 U1.E7(SAIF0_SDATA0/PWM_6/AUART4_TX/GP)
SAIF0_LRCLK: R201.1 U1.G6(SAIF0_LRCLK/PWM_4/AUART4_RTS/GP)
SAIF0_MCLK: R203.1 U1.G7(SAIF0_MCLK/PWM_3/AUART4_CTS/GPI)
SPI2_MISO: RN9.3(PIN3) U1.B3(SSP2_MISO/SSP2_D0/AUART3_RX/SAI) U1.B4(SSP0_DATA7/SSP2_SCK/GPIO2_7)
SPI2_MOSI: RN9.1(PIN1) U1.C3(SSP2_MOSI/SSP2_CMD/AUART2_TX/SA)
SPI2_SCK: RN9.4(PIN4) U1.A3(SSP2_SCK/AUART2_RX/SAIF0_SDATA1)
SPI2_SS: RN9.2(PIN2) U1.C4(SSP2_SS0/SSP2_D3/AUART3_TX/SAIF)
TOUCH_RESET: J13.33 R92.1
UART0_CTS: J20.44(LED_WLAN#) U1.J6(AUART0_CTS/AUART4_RX/DUART_RX/G)
UART0_RTS: J20.45(RESERVED7) U1.J7(AUART0_RTS/AUART4_TX/DUART_TX/G)
UART0_RX: J20.46(LED_WPAN#) U1.G5(AUART0_RX/I2C0_SCL/DUART_CTS/GP)
UART0_TX: J20.47(RESERVED8) U1.H5(AUART0_TX/I2C0_SDA/DUART_RTS/GP)
UART1_RX: R157.2 U1.L4(AUART1_RX/SSP2_CARD_DETECT/PWM_)
UART1_TX: R156.2 U1.K4(AUART1_TX/SSP3_CARD_DETECT/PWM_)
USB0_DM: L29.1 U1.A10(USB0DM)
USB0_DP: L29.4 U1.B10(USB0DP)
USB0_ID: J7.4(P4) R17.2 U1.K8(PWM2/USB0_ID/USB1_OVERCURRENT/G)
USB1_DM: U1.B8(USB1DM) U25.30(USBUP_DM)
USB1_DP: U1.A8(USB1DP) U25.31(USBUP_DP)
USB2SER_RX: Q18.2(SOURCE) U34.19(RXD)
USB2SER_TX: Q20.2(SOURCE) U34.20(TXD)
USB_BOT_DM: L32.1 U25.6(USBDN3_DM/PRT_DIS_M3)
USB_BOT_DP: L32.4 U25.7(USBDN3_DP/PRT_DIS_P3)
USB_DEBUG_DM: L34.1 U34.14(USBDN)
USB_DEBUG_DP: L34.4 U34.15(USBDP)
USB_EXTAL: C148.1 R47.2 U34.22(EXTAL) Y8.3
USB_HUB_RST_B: U17.15(IO1_5) U25.26(RESET_N)
USB_MODEM_DM: L33.4 U25.1(USBDN1_DM/PRT_DIS_M1)
USB_MODEM_DP: L33.1 U25.2(USBDN1_DP/PRT_DIS_P1)
USB_TOP_DM: L31.1 U25.3(USBDN2_DM/PRT_DIS_M2)
USB_TOP_DP: L31.4 U25.4(USBDN2_DP/PRT_DIS_P2)
USB_XTAL: C149.1 R47.1 U34.21(XTAL) Y8.1
USBOTG_OC: U1.D4(SSP2_SS2/SSP2_D5/SSP2_D2/USB0_O) U33.8(O\C\1\)
USBOTG_VBUS_EN: U17.1(IO0_0) U33.3(EN1) U40.13(B4)
VR_ANA: C166.2 C188.1 U4.44(VR_ANA)
VR_DIG: C167.1 C189.1 U4.45(VR_DIG)
VR_PA: C173.1 C174.1 C176.1 L6.1 U4.42(VR_PA)
WIFI_SDIO_CLK: J20.25(PERP0) R193.2
WIFI_SDIO_CMD: J20.29(GND5) R64.2 R194.2
WIFI_SDIO_D0: J20.23(PERN0) R195.2
WIFI_SDIO_D1: J20.27(GND4) R196.2
WIFI_SDIO_D2: J20.28(1.5V_2) R197.2
WIFI_SDIO_D3: J20.30(SMB_CLK) R198.2
WL_RF_1V8: C151.1 C199.1 C214.1 J20.11(REFCLK-) U14.5(VOUT)
WLAN_ACTIVE: J20.49(RESERVED9) R110.1
WLAN_PDN: J20.22(PERST#) U17.6(IO0_5)
WLAN_WAKE: J20.21(GND3) U17.12(IO1_2)
ZB_SPI_MISO: RN8.2(PIN2) U15.29(SPI_MISO/GPIO5) U15.34(SSI_TX/GPIO0)
ZB_SPI_MOSI: RN8.4(PIN4) U15.28(SPI_MOSI/GPIO6)
ZB_SPI_SCK: RN8.1(PIN1) U15.27(SPI_SCK/GPIO7)
ZB_SPI_SS: RN8.3(PIN3) U15.30(SPI_SS/GPIO4)
ZIGBEE_FLASH_ERASE: R145.1 U17.2(IO0_1)
ZIGBEE_GPIO: U1.E9(PWM3/GPIO3_28) U15.33(SSI_RX/GPIO1)
ZIGBEE_LED: R102.1 U15.26(TMR0/GPIO8)
ZIGBEE_RESET_B: R80.1 R146.2 U15.51(R\E\S\E\T\) U17.5(IO0_4)
N20112384: C156.1 C184.1 L10.2 R82.2 U15.44(LREG_BK_FB)
N20121042: D6.A L10.1 U15.43(COIL_BK)
N20123696: D6.C R81.2 U15.45(VBATT)
N20135512: Q4.1(GATE) R75.1 R76.1 R145.2 U15.61(ADC2_VREFL/GPIO39)
N20137474: Q4.3(DRAIN) R77.1 U15.64(ADC2_VREFH/GPIO38)
N20150953: C182.2 J12.1(CTR)
N20151194: C181.1 C182.1 U15.60(RF_RX_TX)
N20157126: U15.50(XTAL_24_IN) Y5.1
N20157653: U15.49(XTAL_24_OUT) Y5.3
N20183643: R9.2 R181.2 U3.12(MDIO)
N20200163: C31.1 R6.2 T1.4(CT1) T1.5(CT2)
N20614471: C177.1 C178.1 L6.2 L7.2
N20623476: C177.2 C194.1 L8.1
N20623914: C179.1 L8.2 L9.1
N20639994: C180.1 C191.2 C193.1 L9.2
N20766165: R15.1 U3.24(RBIAS)
N20769333: C32.1 C33.1 U3.6(VDDCR)
N20787959: L2.1 U1.A16(DCDC_LP)
N20788242: L2.2 U1.B17(DCDC_LN)
N21052242: R49.1 U1.B9(DEBUG)
N21053866: C142.2 U1.A12(XTALI) Y3.1
N21053884: C141.1 U1.B12(XTALO) Y3.3
N21906184: C107.1 F1.2 J5.1
N22010545: R157.1 U15.20(UART1_TX/GPIO14)
N22878041: C108.2 R41.2
N22880531: R39.2 R41.1 R43.1 SW2.1
N24090083: C143.1 U1.D11(RTC_XTALI) Y2.1
N24109192: C144.1 U1.C11(RTC_XTALO) Y2.2
N24612024: ANT1.1(SIGNAL) C181.2
N25260991: C304.1 J7.1(P1) L3.2
N25368576: R78.2 U15.17(UART1_RTS/GPIO17)
N25879518: C193.2 J10.1(CTR) L30.1
N25882006: C191.1 C192.1
N25942077: R125.1 U15.8(ADC7/RTCK/GPIO37)
N26302633: R199.2 U19.25(I2S_DOUT)
N26303165: R200.2 U19.26(I2S_DIN)
N26303698: R201.2 U19.23(I2S_LRCLK)
N26304232: R202.2 U19.24(I2S_SCLK)
N26306493: R203.2 U19.21(SYS_MCLK)
N26311614: C61.1 L12.2 U19.5(VDDA)
N26315679: R128.2 U19.30(VDDD)
N26322683: C68.1 U19.18(CPFILT)
N26324953: C82.1 U19.10(VAG)
N26335790: TP12.1(TP) U19.12(LINEOUT_L)
N26335836: TP11.1(TP) U19.11(LINEOUT_R)
N26352753: R129.1 R134.1 U19.31(CTRL_ADR0_CS)
N26353356: R130.1 U19.32(CTRL_MODE)
N27366059: C104.2 R42.1
N27773305: D12.A L20.2 U20.6(SW)
N27773317: R131.1 R132.2 U20.4(FB)
N28006980: Q9.1(GATE) Q13.3(G) Q14.3(G) U30.4(OUT)
N28006984: Q5.1(D1) Q5.2(D2) Q5.5(D3) Q5.6(D4) Q6.1(D1) Q6.2(D2) Q6.5(D3) Q6.6(D4)
N28007052: Q13.1(D1) Q13.2(D2) Q13.5(D3) Q13.6(D4) Q14.1(D1) Q14.2(D2) Q14.5(D3) Q14.6(D4)
N28007071: Q5.3(G) Q6.3(G) Q9.3(DRAIN) R135.2
N28007120: C204.1 U22.2(B00ST)
N28007130: C204.2 D17.C L16.1 U22.3(SW)
N28007178: R149.2 U22.9(VC)
N28007224: C203.1 R149.1
N28007244: R150.1 U22.10(RTC)
N28007274: R148.1 R176.1 U22.8(FB)
N28567011: L18.1 U28.5(SW)
N28574144: R172.2 U28.3(EN)
N28583550: C218.1 C219.2 R173.1 R174.2 U28.4(FB)
N28633938: C223.1 C224.2 R175.1 R178.2 U29.4(FB)
N28634078: L19.1 U29.5(SW)
N28722713: C303.1 J22.A1(VCC) L21.2
N28726188: C146.2 R205.1 U25.32(XTALOUT) Y7.1
N28726198: C145.1 R205.2 U25.33(XTALIN/CLKIN) Y7.3
N28726415: R177.1 U25.35(RBIAS)
N28726934: C225.1 U25.14(CRFILT)
N28727026: C226.1 U25.34(PLLFILT)
N28727439: R136.1 R137.2 U25.25(HS_IND/CFG_SEL1)
N28728688: R138.2 R147.1 U25.28(SUSP_IND/LOCAL_PWR/NON_REM0)
N28737757: D4.A U33.7(OUT1)
N28745352: J13.73 J13.75 J13.77 R93.1
N28745357: J13.117 R85.1
N28753815: D7.C(CATHODE) U34.7(UART_LED)
N28753820: D8.C(CATHODE) U34.5(USB_LED)
N28753851: D7.A(ANODE) R68.2
N28753854: D8.A(ANODE) R69.2
N28755364: C34.1 R19.2 U34.2(R\E\S\E\T\)
N28758461: C305.1 J8.1(P1) L5.2
N28758635: R18.2 U34.10(CTS)
N28759486: TP15.1(PIN1) U34.1(R\E\S\U\M\E\)
N28759489: TP16.1(PIN1) U34.3(S\U\S\P\E\N\D\)
N28774283: J8.2(P2) L34.2
N28774290: J8.3(P3) L34.3
N28783725: R95.1 R141.1 U25.24(SCL/SMBCLK/CFG_SEL0)
N28784781: R94.1 R142.1 U25.22(SDA/SMBDATA/NON_REM1)
N28787165: C301.1 L24.2 U35.1(VCC_B)
N28847997: U40.10(B3) U40.11(Y4)
N28848006: U40.6(Y2) U40.9(A3)
N28853722: R108.1 U25.12(PRTPWR1) U31.2(IN_A)
N28858706: R144.2 SW5.1
N28858725: R127.2 SW7.1 SW7.3
N28859319: R153.1 SW8.2
N28870429: D11.A L11.2 U16.6(SW)
N28870443: R98.2 R103.1 U16.4(FB)
N28879486: R118.2 R121.2 S1.2(A2)
N28886082: C302.1 J22.B1(VCC_B) L22.2
N28952872: C296.1 D3.1(ANODE2) D3.2(ANODE1) D35.1(ANODE2) D35.2(ANODE1) D36.1(ANODE2) D36.2(ANODE1) D37.1(ANODE2) D37.2(ANODE1) D38.1(ANODE2) D38.2(ANODE1) D39.1(ANODE2) D39.2(ANODE1) D40.1(ANODE2) D40.2(ANODE1) D41.1(ANODE2) D41.2(ANODE1) D42.1(ANODE2) D42.2(ANODE1) L15.1
N28956999: D35.4(CATHODE1) RN6.16(B)
N28957279: D35.3(CATHODE2) RN6.15(B)
N28957286: D36.4(CATHODE1) RN6.14(B)
N28957291: D36.3(CATHODE2) RN6.13(B)
N28957296: D37.4(CATHODE1) RN6.12(B)
N28957304: D37.3(CATHODE2) RN6.11(B)
N28958157: D38.4(CATHODE1) RN6.10(B)
N28958172: D38.3(CATHODE2) RN6.9(B)
N28958816: D39.4(CATHODE1) RN7.16(B)
N28958825: D39.3(CATHODE2) RN7.15(B)
N28958831: D40.4(CATHODE1) RN7.14(B)
N28958836: D40.3(CATHODE2) RN7.13(B)
N28958844: D41.4(CATHODE1) RN7.12(B)
N28958860: D41.3(CATHODE2) RN7.11(B)
N28958863: D42.4(CATHODE1) RN7.10(B)
N28960141: D42.3(CATHODE2) RN7.9(B)
N28976429: C242.2 J23.4 R97.2
N28976672: C197.2 C200.2 J23.3 L27.2 R97.1 R99.2
N28977107: C207.1 C209.1 J23.1 L28.2 R99.1
N28977635: C242.1 R179.2
N29028813: R182.2 U3.13(MDC)
N29028833: R183.2 U3.8(RXD0/MODE0)
N29028836: R184.2 U3.7(RXD1/MODE1)
N29028839: R185.2 U3.11(CRS_DV/MODE2)
N29028854: R186.2 U3.17(TXD0)
N29028859: R187.2 U3.18(TXD1)
N29028863: R188.2 U3.16(TXEN)
N29028931: R180.2 U3.5(XTAL1/CLKIN)
N29031770: J7.3(P3) L29.3
N29031779: J7.2(P2) L29.2
N29031855: J17.2 R165.1
N29039241: L33.3 U35.2(DATA-)
N29039246: L33.2 U35.3(DATA+)
N29040204: J22.A2(DATA+) L31.2
N29040213: J22.A3(DATA-) L31.3
N29040310: J22.B2(DATA+_B) L32.2
N29040319: J22.B3(DATA-_B) L32.3
N29041995: R193.1 U1.A6(SSP0_SCK/GPIO2_10)
N29042001: R194.1 U1.A4(SSP0_CMD/GPIO2_8)
N29042019: R195.1 U1.B6(SSP0_DATA0/GPIO2_0)
N29042022: R196.1 U1.C6(SSP0_DATA1/GPIO2_1)
N29042025: R197.1 U1.D6(SSP0_DATA2/GPIO2_2)
N29042028: R198.1 U1.A5(SSP0_DATA3/GPIO2_3)
N29085144: C253.1 U42.4(NC)
N29085154: R210.2 U42.3(EN)
N29116997: R100.2 R101.2 RN6.6(A)
N29117101: R102.2 R106.2 RN6.8(A)
N29117415: R107.2 R110.2 RN6.4(A)
N29125794: R96.1 U41.13(TEST)
N29128269: C295.1 D45.A(ANODE) Q15.3(GATE) R20.1
N29155506: R152.1 SW6.2
N29157230: R156.1 U15.19(UART1_RX/GPIO15)
N29175701: J9.1(CTR) R166.2 R168.1
N29175849: J14.1(CTR) R167.2 R170.1
N29213138: C297.1 E5.2
N29213145: C298.1 E6.2
N29241645: R206.2 R207.2 RN6.2(A)
N29243151: C299.1 J16.1 R209.2
N29246306: Q16.3(DRAIN) R211.2
N29246425: D3.3(CATHODE2) R211.1
N29256208: D3.4(CATHODE1) R46.2
N29272408: R11.1 T1.12(YLED-)
N29272682: R10.1 T1.9(GLED+)
N29297998: Q17.3(DRAIN) Q18.3(DRAIN)
N29298001: Q19.3(DRAIN) Q20.3(DRAIN)

Pads without a net: D44 2; FL1 3 5 6 7 9 10; J8 4; J11 3 5; J13 3 9 10 14 15 16 20 21 22 26 27 28 32 34 35 37 40 44 46 50 51 52 53 55 56 57 58 59 61 63 81 85 87 89 91 107 118 120; J20 5 7 15 16 17 18 19 20 31 33 34 35 36 37 38 39 40 51; SW2 3 4; SW5 3 4; SW6 3 4; SW8 3 4; U1 A2 B1 B2 B14 C1 C2 D1 D2 E1 E3 F3 F5 F6 G1 G2 H6 H7 J1 J2 J3 J4 J5 K5 K6 L1 L5 L6 L8 M1 M5 M7 M8 M9 N1 N5 N9 P9 T17; U2 A2 E2 R7; U3 4; U4 6 7 9 10 11 13 17 18 21 22 23 26 27 28 29 30 31 41 49 50 51 52 53 57 58 59 60; U5 1 2 3 4 5 6 10 11 14 15 20 21 22 23 24 25 26 27 28 33 34 35 38 39 40 45 46 47 48; U14 4; U15 1 2 3 4 5 6 7 13 14 15 16 18 21 22 23 24 25 31 32 35 36 37 38 39 40 41 42 47 48 52 53 54 56 57 59 62 63 65 66 67 68 69 70 71 72 73 74 80 81 82 83 89 90 91 92 98 99 100 101 102 103 107 108 109 110 111 112 113 114 116 117 118 119 120 121 122 123 125 126 127 128 129 130 131 132 134 135 136 137 138 139 140 141 142 143 144 145; U17 10; U19 8 9 13 14 17 19 22 28; U25 8 9 11 20 21; U34 4 6 8 9 12 18 24; U40 1 2 3

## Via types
v1: diameter 0.508, hole 0.305, TOP to BOTTOM, 2073 vias
v2: diameter 1.016, hole 0.838, TOP to BOTTOM, 4 vias

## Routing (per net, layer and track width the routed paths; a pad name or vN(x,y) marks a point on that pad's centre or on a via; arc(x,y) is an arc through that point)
3V3_DEBUG: length 5.4
  TOP w0.3: C205.1 107.49,7.85 C206.1 107.51,7.9 107.04,8.37 105.64,8.37 v1(105.53,8.25) ; U34.16 105.26,8.52 v1(105.53,8.25) ; v1(105.53,8.25) 105.65,8.25 105.83,8.43 105.83,9 U34.17
3V3_GATED: length 84.8
  TOP w0.1: C215.1 15.54,50.9 J20.3
  TOP w0.3: J20.4 J20.2 ; J20.2 23.35,51.3 22.98,51.67 v1(22.98,51.95) ; J20.2 24.98,51.3 25.1,51.42 v1(25.11,51.42) ; D44.3 72.81,77.81 72.09,78.53 R204.1 72.09,79.07 71.89,79.27 71.47,79.27 71.42,79.23 v1(71.29,79.23) 71.13,79.07 C294.1 ; 25.19,48.63 24.65,48.1 J20.10 ; 25.19,48.63 25.19,48.25 25.11,48.18 v1(25.11,48.03) 24.98,47.91 24.98,47.79 24.5,47.3 J20.12 ; 25.19,48.63 25.19,48.73 25.11,48.81 v1(25.11,48.88) ; J20.3 16.46,50.9 17.1,50.26 v1(17.1,50.26) ; R128.1 102.29,34.12 L12.1 102.81,33.59 102.81,30.47 102.5,30.16 v1(102.5,30.07)
  TOP w0.5: C284.1 31.97,59.87 C286.1 32.32,59.86 v1(32.71,59.47) ; C284.1 32.09,61.03 33.16,61.03 L19.2 ; C284.1 C285.1 ; v1(32.47,62.28) 32.18,62.57 C223.2 ; v1(34.09,61.14) 34.08,61.13 L19.2 ; L19.2 33.25,61.96 33.39,62.1 34.1,62.1 v1(34.1,62.09) ; L19.2 33.25,60.81 ; v1(32.23,59.04) 32.99,58.28 C221.1 33.25,58.36 33.25,60.81 ; C285.1 32.06,61.78 v1(32.43,61.41) ; C285.1 31.97,62.56 C223.2 ; C223.2 31.96,63.38 R178.1 32.14,63.39 v1(32.65,62.88) ; 33.25,60.81 33.95,60.11 v1(34.15,60.11) ; v1(30.29,46.05) 30.56,46.05 30.93,46.42 32.59,46.42 33.51,47.34 33.51,47.93 v1(33.58,48)
  BOTTOM w0.1: 38.82,45.48 38.82,45.43 38.82,45.43 ; 38.82,45.48 38.82,45.62 39.37,46.17 39.81,46.17 R9.1 ; 38.82,45.48 38.77,45.48 ; v1(34.24,50.34) 34.24,49.82 R14.2 ; R77.2 111.05,50.8 v1(111.58,50.26) ; 38.82,45.43 38.39,45 R12.1 38.31,45.88 R13.2 38.35,45.9 38.77,45.48 ; 38.82,45.43 38.83,45.43 38.91,45.5 39.05,45.5 39.46,45.91 40.31,45.91 40.66,45.57 41.88,45.57 41.92,45.61 41.92,45.62 v1(41.92,45.62) ; v1(14.09,37.83) 14.46,37.47 14.46,37.4 16.49,35.36 16.54,35.36 16.95,34.94 17.57,34.94 17.84,35.21 17.84,35.24 18.11,35.51 R64.1 ; 38.77,45.48 v1(38.75,45.48)
  BOTTOM w0.3: 23.33,51.31 C152.1 ; 23.33,51.31 C154.1 ; 23.33,51.31 22.98,51.66 v1(22.98,51.95) ; 30.56,46.24 30.51,46.18 30.48,46.18 ; 30.56,46.24 30.54,46.24 30.48,46.18 ; 30.56,46.24 C250.1 ; v1(25.11,48.88) 24.87,48.63 24.48,48.63 C287.1 C147.1 ; R81.1 98.2,56.21 v1(98.2,56.19) ; C58.1 102.5,30.74 102.5,30.16 ; C29.1 33.48,48.09 v1(33.58,48) 33.59,47.99 U3.9 ; 30.48,46.18 30.41,46.18 v1(30.29,46.05) 29.66,46.05 29.66,46.04 28.96,46.04 L1.2 28.92,46.72 C249.1 ; U19.20 102.81,30.47 102.5,30.16 ; v1(11.28,53.94) 11.28,54.06 11.48,54.25 15.64,54.25 16.3,53.6 17.08,54.38 C198.1 ; v1(25.11,48.03) 24.98,48.03 24.65,47.7 C288.1 24.37,47.67 C155.1 23.36,47.65 C216.1 ; C150.1 18.25,50.75 v1(18.79,50.75) ; v1(71.29,79.23) 72.76,79.23 U41.7 ; v1(102.5,30.07) 102.5,30.16 ; C183.1 92.8,56.74 C157.1 ; C271.1 v1(25.11,51.42)
  BOTTOM w0.5: v1(93.05,58.45) 92.8,58.2 C157.1 ; v1(92.75,55.9) 92.78,55.93 C183.1 ; R82.1 92.71,53.64 v1(92.5,53.85)
3V3_GATED_EN: length 81.7
  TOP w0.1: v1(36.55,65.97) 36.4,65.97 35.05,64.62 33.49,64.62 33.01,65.12 33.01,65.66 33.3,65.95 U29.3 ; v1(70.65,68.75) 70.5,68.59 70.5,68.09 70.36,67.96 v1(70.36,67.72)
  INT1 w0.1: v1(17.71,50.24) 17.77,50.18 19.95,50.18 20.88,51.12 20.88,52.29 22.19,53.6 23.55,53.6 23.6,53.55 27.22,53.55 28.43,54.77 28.8,54.77 31.4,57.37 31.74,57.37 32.07,57.37 32.41,57.37 32.41,57.37 33.09,57.37 33.09,57.36 33.58,57.36 33.59,57.38 34.42,57.38 34.43,57.37 35.01,57.37 35.02,57.36 35.74,57.36 36.45,58.06 36.45,58.58 36.47,58.6 36.47,58.94 36.45,58.96 36.45,65.86 v1(36.55,65.97) 36.57,65.98 37.92,65.98 44.57,72.63 45.62,72.63 v1(45.85,72.87)
  BOTTOM w0.1: v1(70.36,67.72) 70.36,67.43 70.17,67.24 U17.3 ; v1(17.71,50.24) 17.65,50.3 17.65,50.56 17.36,50.86 R143.1 16.54,51.7 16.3,51.7 ; v1(45.85,72.87) 46.12,72.87 46.47,73.21 66.47,73.21 67.73,71.95 67.73,70.61 68.23,70.1 69.7,70.1 69.73,70.07 69.91,70.07 70.5,69.49 70.5,68.91 v1(70.65,68.75)
3V3_ISM: length 25.8
  TOP w0.3: 25.77,61.53 U42.5 ; U42.5 25.59,61.73 C293.1 25.01,63.19 v1(24.54,62.72) ; U42.5 26.24,61.55 26.34,61.44 v1(26.43,61.44) ; v1(19.43,64.53) 18.3,63.39 18.3,62.91
  INT1 w0.3: v1(24.27,58.79) 24.12,58.79 23.29,59.62 23.29,60.06 v1(23.18,60.17)
  BOTTOM w0.3: U4.43 23.78,67.62 v1(23.94,67.78) 23.94,67.95 24.75,68.75 24.75,69.98 C170.1 v1(24.81,71.16) ; v1(24.47,61.83) 24.47,61.39 24.67,61.19 C163.1 24.6,61.12 U4.55 ; C165.1 25.42,58.91 25.03,58.52 24.55,58.52 v1(24.27,58.79) ; v1(23.18,60.17) 23.34,60.17 U4.56 24.43,60.62 C161.1 24.86,60.19 C164.1 ; U4.1 23.16,58.99 C160.1 22.8,58.64 22.8,58.31 v1(22.84,58.27) ; U4.19 15.63,62.62 15.46,62.44 15.1,62.44 C162.1 14.55,62.3 v1(14.21,61.96) ; C169.1 19.72,70 C168.1 19.64,69.59 v1(19.64,68.51) 19.66,68.5 U4.35
3V3_MAIN: length 79.4
  TOP w0.3: v1(33.41,54.69) 33.41,51.33 31.17,49.09 30.5,49.09 29.71,48.31 29.71,45.81 28.54,44.63 28.54,42.81 26.87,41.14 26.87,39.04 25.95,38.12 v1(25.95,37.9)
  BOTTOM w0.1: R212.1 84.6,87.55 L15.2
  BOTTOM w0.3: v1(33.25,55.41) 33.31,55.47 33.31,57.08 31.69,58.7 31.66,58.7 30.94,59.42 30.94,61.56 30.91,61.59 30.91,62.85 30.11,63.66 30.11,65.53 33.48,68.91 33.5,68.91 33.99,69.4 v1(35.77,69.4) 36.06,69.4 36.22,69.55 v1(36.37,69.55) ; U25.5 v1(30.55,29.07) 30.56,29.06 30.56,28.43 ; U25.29 34.26,34.2 v1(34.29,34.23) 34.29,34.75 C230.1 ; U25.15 27.68,33.1 27.18,33.1 27.11,33.04 v1(26.83,33.04) 26.77,33.1 26.59,33.1 26.24,33.45 C228.1 ; v1(81.35,87.6) 82.35,88.6 85.77,88.6 86.32,89.14 L15.2 ; U25.10 27.78,30.56 27.45,30.24 v1(27.45,30.21) 27.43,30.19 C211.1 ; C229.1 30.2,36.35 v1(30.4,36.35) 30.4,36.32 30.55,36.16 U25.23 ; v1(33.05,35.27) 32.76,35.27 U25.27 32.55,36.9 R137.1 33.71,37.51 R138.1 ; C210.1 33.35,30.05 v1(33.28,30.12) 33.28,30.66 U25.36
  BOTTOM w0.5: C281.1 25.25,42.17 C85.1 ; C281.1 25.73,42.53 25.77,42.49 v1(25.92,42.49) ; C281.1 25.12,42.65 25.12,42.78 24.87,43.03 C283.1 25.33,43.5 25.52,43.31 25.52,43.28 v1(25.67,43.13) ; 21.46,41.96 21.19,41.96 v1(20.29,41.06) ; 21.46,41.96 21.11,41.59 v1(21.11,41.03) ; 21.46,41.96 L18.2 ; 25.45,41.62 25.64,41.81 25.8,41.81 25.88,41.88 v1(25.88,41.88) ; 25.45,41.62 C85.1 ; 25.45,41.62 25.46,41.62 C282.1 ; C85.1 22.45,41.62 L18.2 ; L18.2 22.12,42.76 22.26,42.9 22.26,43.03 R174.1 22.38,43.9 22.39,43.91 ; L18.2 22.12,41.06 v1(22.11,41.06)
  vias: v1(25.39,38.19) v1(26.46,37.57) v1(32.52,55.44) v1(32.75,54.66) v1(33.95,55.37) v1(36.23,68.97)
4V2_BACKUP: length 74.1
  TOP w0.1: v1(74.44,37) 74.82,36.62 R155.1 ; R210.1 29.27,57.34 ; R210.1 28.33,57.34 ; R210.1 28.8,56.87 ; 25.36,57.82 C292.1 24.77,57.1
  TOP w0.3: U42.1 25.77,58.41 25.34,57.97 25.34,57.13 C292.1
  TOP w0.5: Q6.4 74.62,33.1 v1(74.99,33.47) 74.75,33.71 74.17,33.71 73.95,33.93 73.95,33.94 v1(73.89,34) 73.7,34.19 Q13.4 ; v1(34.19,65.04) 34.3,65.04 35.2,65.95 U29.1 35.2,67.47 C222.1 34.88,68.3 ; v1(35.05,68.81) 35.05,68.49 34.88,68.31 34.88,68.3 ; 34.88,68.3 34.48,68.69 34.45,68.69 v1(34.42,68.73) 34.35,68.73 34.29,68.78 33.08,68.78 29.99,65.7 29.99,62.07 29.6,61.69 29.6,61.68 29.61,61.67 29.61,61.2 29.56,61.16 29.56,56.97 29.01,56.42 28.98,56.42 28.73,56.18 26.12,56.18 26.06,56.24 25.52,56.24 25.36,56.4 C292.1
  BOTTOM w0.1: 16.78,39.88 16.87,39.96 U28.1 ; 96.86,10.08 U20.2 96.86,10.73 ; 97.34,9.92 C196.1 99.17,9.92 ; R158.1 98.62,8.81 v1(98.33,9.11) ; v1(73.89,34) 73.62,34.28 73.36,34.28 73.08,34 73.08,33.94 72.84,33.7 72.62,33.7 72.59,33.67 72.25,33.67 72.25,33.68 71.76,33.68 R135.1 ; U30.5 75.01,33.5 75.18,33.66 76.54,33.66 76.67,33.8 76.67,34.91 75.62,35.96 74.78,35.96 74.44,36.29 v1(74.44,37)
  BOTTOM w0.3: v1(26.84,55.43) 26.83,55.41 ; U16.2 84.73,53.64 84.47,53.39 C185.1 ; 84.02,50.57 84.02,51.63 83.93,51.73 83.93,51.98 83.93,52.32 ; L20.1 93.75,18.74 ; L20.1 92.2,17.62 ; L20.1 93.75,16.51 ; L20.1 95.3,17.62 ; U20.2 97.36,10.41 97.7,10.06 98.12,10.06 C196.1
  BOTTOM w0.5: C185.1 83.93,52.32 v1(83.81,52.32) ; 75.01,33.5 v1(74.99,33.47) 74.32,32.81 C208.1 ; R172.1 14.97,40.05 15.13,39.88 15.49,39.88 C220.1 16,39.88 16.78,39.88 ; v1(84.6,52.43) 84.62,52.45 84.62,53.01 84.83,53.22 84.89,53.22 U16.2 ; 84.02,49.31 85.02,50.31 v1(85.02,50.32) ; 84.02,49.31 84.02,50.57 84.04,50.57 84.37,50.91 v1(84.39,50.91) ; 84.02,49.31 L11.1 84.66,48.9 85.3,49.53 85.33,49.53 v1(85.56,49.76) ; U28.1 17.49,39.96 ; 17.49,39.96 17.85,39.96 v1(17.95,40.06) ; 17.49,39.96 v1(18.31,39.14) ; v1(98.33,9.11) 98.26,9.18 C196.1
  vias: v1(73.83,37.18) v1(75.23,37.5) v1(79.84,42.32) v1(80.5,42.26) v1(80.53,42.97) v1(81.17,43.02) v1(81.14,42.34) v1(81.86,42.3) v1(82.82,42.26) v1(91.68,18.5) v1(91.66,17.57) v1(91.68,16.59) v1(91.61,15.76) v1(92.8,19) v1(92.99,15.81) v1(94.38,15.78) v1(94.45,19) v1(95.79,17.78) v1(95.78,16.77) v1(95.85,18.75) v1(95.85,15.78) v1(97.69,9.13) v1(98.94,9.12)
4V2_BUCK: length 32.2
  TOP w0.1: 79.28,39.34 79.41,39.47 79.44,39.47 80.46,38.46 80.46,35.21 80.46,35.21 80.46,34.35 v1(80.73,34.08) ; 79.28,39.34 78.59,39.34 78.48,39.23 v1(78.46,39.23) ; 79.28,39.34 79.3,39.34 79.34,39.38 ; 73.81,31.11 Q5.4 73,31.11 ; 80.97,34.19 C276.1 81.44,34.65
  TOP w0.5: v1(80.73,34.08) 81.33,34.08 C276.1 ; v1(80.73,34.08) 81.8,35.15 C277.1 ; v1(80.73,34.08) 80.73,33.48 ; 80.73,33.48 80.86,33.35 C275.1 ; 80.73,33.48 76.94,29.69 76.35,29.69 76.33,29.66 75.05,29.66 74.55,29.66 74.52,29.69 73.75,29.69 73.4,30.03 Q5.4
  BOTTOM w0.1: U22.7 78.46,37.72 v1(78.46,39.23)
  BOTTOM w0.3: L16.2 81.87,32.02 80.15,33.74 80.15,34.71 U22.1 81.25,34.73 81.81,35.29
  BOTTOM w0.5: 81.81,35.29 C201.1 80.73,34.09 v1(80.73,34.08)
4V2_PG: length 85.8
  TOP w0.1: v1(100.56,85.66) 100.51,85.66 100.51,85.7 100.58,85.77 100.58,86.58 98.43,88.74 98.43,95.62 97.62,96.42 S1.1 ; R155.2 76,36.63 v1(76.65,37.28) 76.65,37.5 76.67,37.51 76.67,38.51 76.7,38.55 76.7,38.56 79.75,41.61 83.68,41.61 86.92,44.85 86.92,44.94 v1(86.93,44.96)
  INT1 w0.1: v1(92.09,48.03) 102.21,58.16 102.21,70.95 103.54,72.28 103.54,76.01 102.66,76.9 102.66,77.5 100.25,79.92 99.74,79.92 98.74,80.92 98.74,84.13 100.27,85.66 v1(100.56,85.66)
  BOTTOM w0.1: v1(92.09,48.03) 91.83,47.78 91.27,47.78 89.75,46.26 87.79,46.26 87.64,46.1 87.64,46.1 87.01,45.47 87.01,45.03 v1(86.93,44.96) ; 77.68,37.28 77.95,37.55 U22.6 ; 77.68,37.28 77.58,37.18 77.58,36.57 76.98,35.97 76.06,35.97 75.67,36.37 U30.2 ; 77.68,37.28 v1(76.65,37.28)
5V: length 65.3
  TOP w0.1: J13.8 95.89,51.61 94.59,51.61 94.26,51.94 C279.1 ; J13.7 102.73,51.63 103.11,52.01 103.11,52.08 C259.1 ; J13.11 J13.13 ; J13.4 J13.2 95.52,50.53 94.65,50.53 ; J13.41 J13.39
  TOP w0.3: J13.41 99.73,60.13 ; 99.73,60.13 v1(99.73,60.15) ; 99.73,60.13 100.23,59.63 J13.39 102.77,59.63 103.1,59.31 C256.1 ; J13.7 100.03,51.63 100,51.6 ; 94.3,48.15 94.24,48.15 v1(93.7,48.69) 94.07,49.07 C262.1 94.11,49.41 94.84,50.13 J13.2 ; C259.1 103.34,52.37 103.07,52.63 J13.11 99.73,52.63 99.73,52.64 ; C279.1 93.68,51.44 93.68,50.78 94.07,50.38 C278.1 94.3,50.44 94.57,50.44 94.76,50.63 J13.4 ; 99.66,52.64 100.15,53.13 J13.13 101.66,53.11 C258.1
  TOP w0.5: 100,51.6 99.73,51.88 99.73,52.64 99.66,52.64 99.39,52.91 99.39,59.81 v1(99.73,60.15)
  BOTTOM w0.3: C280.1 89.47,56.68 C186.1 89.48,57.08 90.2,56.37 90.2,54.18 D11.C 89.01,54.78 R98.1
  BOTTOM w0.5: v1(93.7,48.69) 93.48,48.69 92.96,49.22 91.83,49.22 91.35,49.69 91.35,52.44 D11.C ; v1(99.73,60.15) 99.17,60.7 98.02,60.7 97.96,60.76 97.55,60.76 97.47,60.85 94.12,60.85 93.89,60.61 93.86,60.61 91.25,58 91.25,57.31 90.62,56.68 C280.1
5V_DEBUG: length 42.2
  TOP w0.1: 104.59,19.16 R69.1 ; 104.59,19.16 R68.1 ; 104.59,19.16 104.59,18.62 v1(104.54,18.56) ; v1(101.86,9.37) 101.76,9.47 101.42,9.47 101.6,9.64 101.6,10.08
  TOP w0.3: C35.1 100.74,9.78 C134.1 ; C35.1 101.37,10.31 101.66,10.02 101.66,9.56 102.65,8.57 102.65,7.43 105.05,5.03 107.69,5.03 108.07,4.65 L5.1 ; C35.1 101.5,10.54 102.49,10.54 ; v1(108.51,16.57) 108.38,16.44 108.38,16.37 108.28,16.27 R19.1
  BOTTOM w0.1: v1(108.51,16.57) 108.86,16.57 R214.2 109.13,15.84 Q20.1 110,14.23 110,13.28 109.16,12.44 Q18.1 ; 105.16,13.82 105.13,13.79 Q19.1
  BOTTOM w0.5: 105.58,17.52 107.94,17.52 108.51,16.95 v1(108.51,16.57) ; 105.58,17.52 105.65,17.45 105.65,16.75 105.16,16.26 105.16,11.72 104.52,11.08 Q17.1 102.46,9.37 v1(101.86,9.37) ; 105.58,17.52 v1(104.54,18.56)
5V_LCD_EN: length 23.4
  TOP w0.1: v1(85.3,55.2) 83.1,55.2 82.7,55.6 82.7,58.1 v1(82.6,58.2)
  BOTTOM w0.1: v1(82.6,58.2) 82.5,58.3 79.6,58.3 77.9,60 77.9,60.2 77.65,60.45 76.6,60.45 70.31,66.74 U17.4 ; U16.3 85.31,55.19 v1(85.3,55.2)
5V_MAIN: length 63.1
  TOP w0.1: D45.C 20.18,16.22 ; D45.C 19.39,15.56 ; D45.C 20.18,14.9 ; D45.C 20.97,15.56 ; R44.1 19.56,19.83 ; R44.1 19.09,20.3 ; R44.1 18.62,19.83 ; 15.89,18.83 15.89,19.34 ; 15.89,19.34 15.28,19.34 ; 15.89,19.34 16.49,19.34 ; TVS2.2 21.2,16.78 ; TVS2.2 20.9,16.48 ; TVS2.2 20.6,16.78
  TOP w0.3: C202.1 77.71,34.78 77.7,34.78 77.7,34.35 v1(77.65,34.3)
  TOP w0.5: 68.45,41.13 C105.1 ; 68.45,41.13 68.51,41.19 C104.1 ; 68.45,41.13 68.45,41.14 v1(69.53,42.22) ; v1(11.37,20.34) 11.55,20.15 11.55,20.15 11.93,19.77 F1.1 ; 15.89,19.34 15.89,20.21 v1(16.2,20.53) ; F1.1 14.82,19.77 v1(15.57,20.53) ; F1.1 13.66,20.8 ; F1.1 13.66,18.81
  PWR w1: 23.1,21.35 23.09,21.35
  BOTTOM w0.3: 18.3,14.04 Q15.2 ; Q15.2 19.56,13.29 ; Q15.2 19.56,14.79 ; 13.35,16.06 Q15.4 13.35,12.02 ; v1(77.65,34.3) 77.65,34.31 78.05,34.71 78.1,34.71 U22.5 U22.4 ; 63.05,44.44 64.11,44.44
  BOTTOM w0.5: 64.11,44.44 64.62,43.92 65.94,43.92 66.93,42.93 67.19,42.93 67.48,42.64 67.73,42.64 68.25,42.12 68.51,42.12 ; Q15.2 19.95,14.04 20.81,13.19 v1(20.81,13.12) ; v1(16.72,20.48) 16.94,20.69 16.94,21.17 18.01,22.25 C233.1 ; C233.1 18.14,22.27 v1(18.14,24.31) ; C233.1 18.73,22.25 19.33,21.66 19.33,20.56 v1(19.38,20.51) ; C233.1 18.11,21.22 ; C233.1 18.11,23.11 ; 18.11,21.22 18.11,21.21 v1(17.46,20.56) ; 18.11,21.22 v1(18.8,20.53) ; 68.51,42.12 69.43,42.12 v1(69.53,42.22) ; 68.51,42.12 68.51,41.82 68.92,41.41 69.06,41.41 C106.1 ; v1(18.14,25.21) 18.04,25.21 17.49,24.66 17.49,23.95 18.11,23.33 18.11,23.11 ; v1(11.36,18.82) 11.26,18.72 11.26,14.59 11.8,14.04 Q15.4 14.8,14.04 16.86,11.98 v1(17.1,11.98) ; 18.11,23.11 v1(18.96,23.96)
  vias: v1(11.55,24.5) v1(11.95,18.48) v1(12.28,20.29) v1(12.8,18.52) v1(13.55,18.54) v1(13.7,24.66) v1(14.51,18.72) v1(17.07,11.03) v1(17.48,11.52) v1(18.63,17.5) v1(18.98,15.25) v1(19.39,10.49)
5V_MAIN_PRESENT: length 130.8
  TOP w0.1: v1(50.67,43.3) 50.67,43.27 50.65,43.25 50.65,42.96 49.84,42.15 48.53,42.15 47.52,41.13 41.3,41.13 38.75,38.59 v1(38.75,38.44) ; v1(12.56,25.64) 12.56,26.51 13.01,26.97 18.04,26.97 18.8,26.2 21.73,26.2 22.19,25.73 28.86,25.73 34.36,25.73 34.79,26.16 36.07,26.16 v1(36.27,25.96) ; R44.2 19.06,18.81 18.57,18.32 v1(18.45,18.32) ; v1(41.38,34.54) 41.42,34.5 53.19,34.5 v1(54.59,33.1)
  BOTTOM w0.1: v1(50.67,43.3) 50.67,43.3 50.68,43.29 51.25,43.29 51.5,43.54 51.59,43.54 51.69,43.63 U1.D3 ; J5.2 18.54,7.77 21.3,10.53 21.3,17.21 20.06,18.46 18.58,18.46 v1(18.45,18.32) 18.29,18.16 14.12,18.16 14.04,18.25 14.04,19.44 13.19,20.29 13.19,20.29 12.72,20.76 11.52,20.76 11.15,21.13 11.15,24.67 11.7,25.22 12.14,25.22 v1(12.56,25.64) ; v1(38.75,38.44) 39.02,38.17 39.02,38.13 41.48,35.68 41.48,34.66 v1(41.38,34.54) 41.38,32.13 39.81,30.56 39.81,30.46 36.47,27.11 36.47,26.15 v1(36.27,25.96) ; U30.1 75.01,37 74.42,37.59 72.68,37.59 71.42,36.33 71.22,36.33 70.34,35.44 70.34,32.41 69.67,31.75 69.67,30.36 69.27,29.96 63.5,29.96 62.95,30.51 62.41,30.51 59.63,33.28 59.63,33.29 58.95,33.97 55.59,33.97 54.73,33.1 v1(54.59,33.1)
5V_USB: length 18
  BOTTOM w0.3: 89.42,10.57 C195.1 ; C195.1 90.34,11.17 ; C195.1 90.79,10.57 91.35,10.01 91.35,7.64 C232.1 91.65,7.6 92.39,8.34 D12.C 92.84,8.16 R132.1 ; 21.59,23.94 22.79,23.94 ; 84.35,9.4 84.29,9.34 U33.2 84.29,7.66 84.3,7.65
  BOTTOM w0.5: 91.55,8.6 91.56,8.61 D12.C ; v1(20.5,20.06) 20.09,20.47 20.09,23.1 20.62,23.63 20.49,23.63 20,24.13 C231.1 ; v1(24.43,19.87) 24.27,20.03
  vias: v1(21.3,20.06) v1(22.14,20.1) v1(22.91,20.09) v1(23.69,20.06) v1(87.01,9.71) v1(87.05,9) v1(87.07,7.46) v1(87.75,8.2) v1(87.91,7.53) v1(88.23,9.18) v1(88.97,9.85)
5V_USB_REG_EN: length 104.8
  TOP w0.1: v1(13.95,26.15) 14.36,26.56 17.84,26.56 18.61,25.79 21.45,25.79 21.92,25.33 34.95,25.33 v1(36.12,24.16)
  INT1 w0.1: v1(36.12,24.16) 36.18,24.21 37.04,24.21 39.88,21.37 61.53,21.37 61.97,20.93 63.22,20.93 63.66,20.49 65.08,20.49 65.53,20.94 67.66,20.94 68.15,21.43 68.68,21.43 68.98,21.72 69.31,21.72 80.08,21.72 83.6,18.2 83.6,18.09 93.7,8 94.18,8 95.28,6.9 96.9,6.9 97.29,7.29 v1(97.37,7.29)
  BOTTOM w0.1: v1(97.37,7.29) 97.55,7.47 97.5,7.53 97.5,7.87 97.61,7.98 97.61,8.31 97.47,8.31 96.86,8.92 U20.3 ; U40.8 13.01,33.24 13.36,32.9 13.36,30.09 12.62,29.36 12.62,27.03 12.77,26.88 13.21,26.88 v1(13.95,26.15)
